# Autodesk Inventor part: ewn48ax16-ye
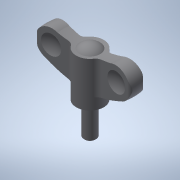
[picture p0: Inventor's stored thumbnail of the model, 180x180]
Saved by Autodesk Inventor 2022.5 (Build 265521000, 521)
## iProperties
Created: 2017-05
Part Number: ewn48ax16-ye
Material: 一般
Document SubType Name: Modeling
Designer: imaocorp
Density: 1 g/cm^3
Appearance: 既定
Author: imaocorp
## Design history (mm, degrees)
node "ewn48ax16-ye.x_t1"
node "ewn48ax16-ye"
node "Base1"
